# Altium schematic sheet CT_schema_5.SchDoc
size 294 x 159 mm
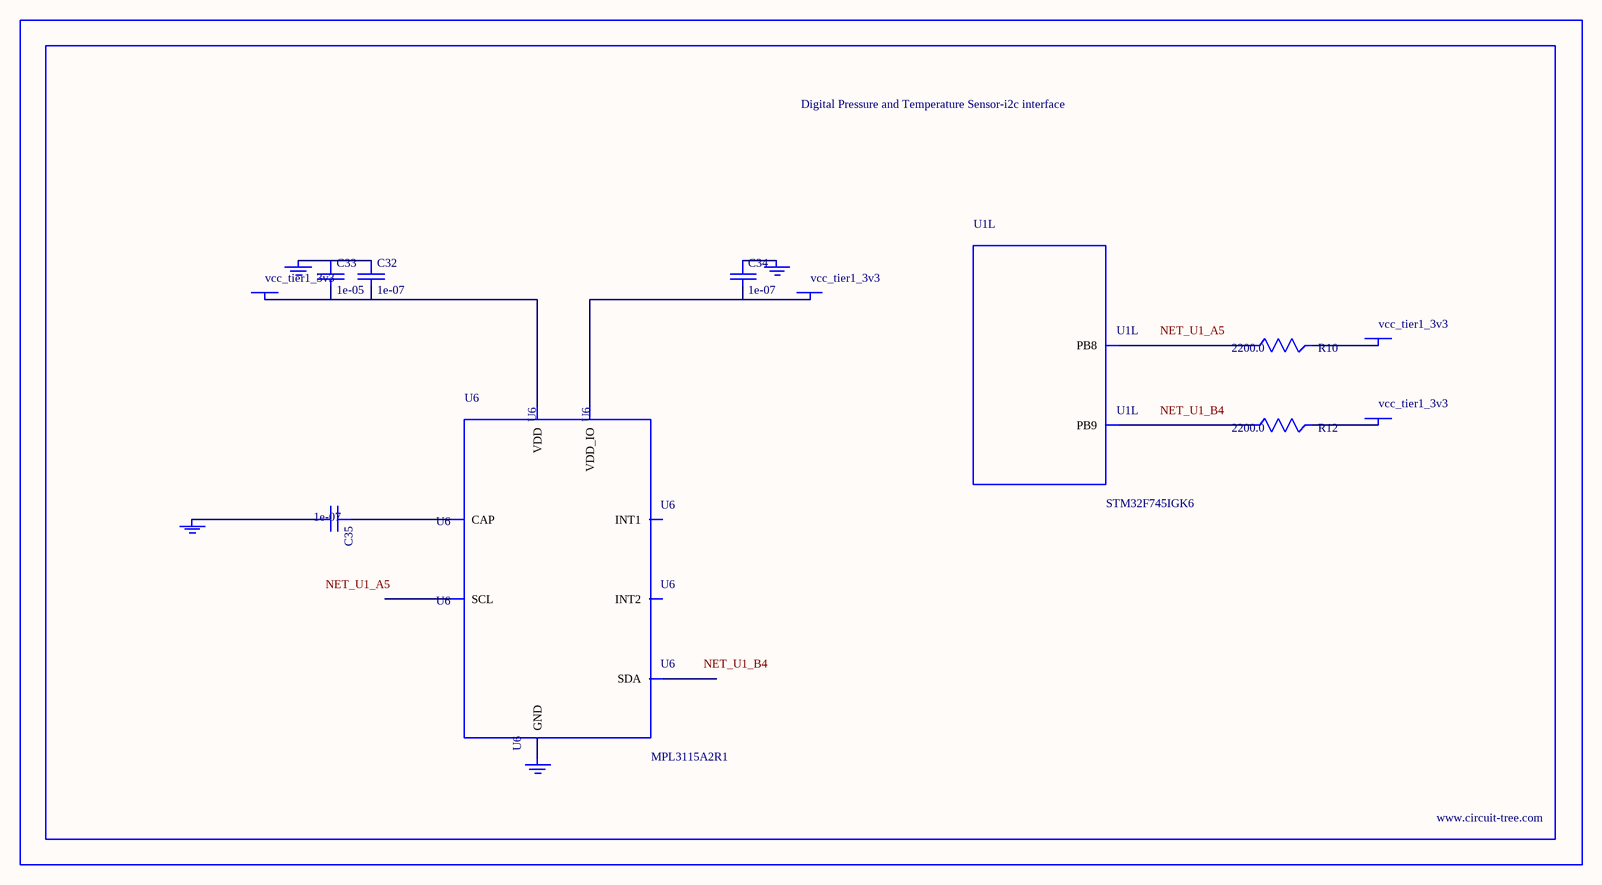
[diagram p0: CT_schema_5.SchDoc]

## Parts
BORDER4  (no value)
C32  1e-07  [C0402]
C33  1e-05  [C0805]
C34  1e-07  [C0402]
C35  1e-07  [C0402]
GND_INSTANCE_4_0  (no value)
GND_INSTANCE_4_1  (no value)
GND_INSTANCE_4_2  (no value)
GND_INSTANCE_4_3  (no value)
POWER_INSTANCE_4_0  vcc_tier1_3v3
POWER_INSTANCE_4_1  vcc_tier1_3v3
POWER_INSTANCE_4_2  vcc_tier1_3v3
POWER_INSTANCE_4_3  vcc_tier1_3v3
R10  2200.0  [R0603]
R12  2200.0  [R0603]
U1  STM32F745IGK6  [UFBGA176_25]  (part L of 16)
U6  MPL3115A2R1  [LGA-8]

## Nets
NetC32_1: C32.1 C33.1 GND_INSTANCE_4_0.0(GND)
NetC32_2: C32.2 C33.2 POWER_INSTANCE_4_0.0(PWR) U6.1(VDD)
NetC34_1: C34.1 GND_INSTANCE_4_2.0(GND)
NetC34_2: C34.2 POWER_INSTANCE_4_1.0(PWR) U6.4(VDD_IO)
NetC35_1: C35.1 U6.2(CAP)
NetC35_2: C35.2 GND_INSTANCE_4_1.0(GND)
NetGND_INSTANCE_4_3_0: GND_INSTANCE_4_3.0(GND) U6.3(GND)
NetPOWER_INSTANCE_4_2_0: POWER_INSTANCE_4_2.0(PWR) R10.2
NetPOWER_INSTANCE_4_3_0: POWER_INSTANCE_4_3.0(PWR) R12.2
NetR10_1: R10.1 U1.A5(PB8)
NetR12_1: R12.1 U1.B4(PB9)

Not connected (* = marked no-connect by the designer): U6 5(INT2) 6(INT1) 7(SDA) 8(SCL)

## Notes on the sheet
- Labels drawn without touching a wire or pin: NET_U1_A5, NET_U1_B4

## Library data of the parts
BORDER4 = BORDER_PAGE4
C32 C34 C35 = C0402C104K3RACTU
C33 = C0805C106K8RACTU
GND_INSTANCE_4_0-GND_INSTANCE_4_3 = GND
POWER_INSTANCE_4_0-POWER_INSTANCE_4_3 = PWR
R10 R12 = RC0603JR-072K2L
